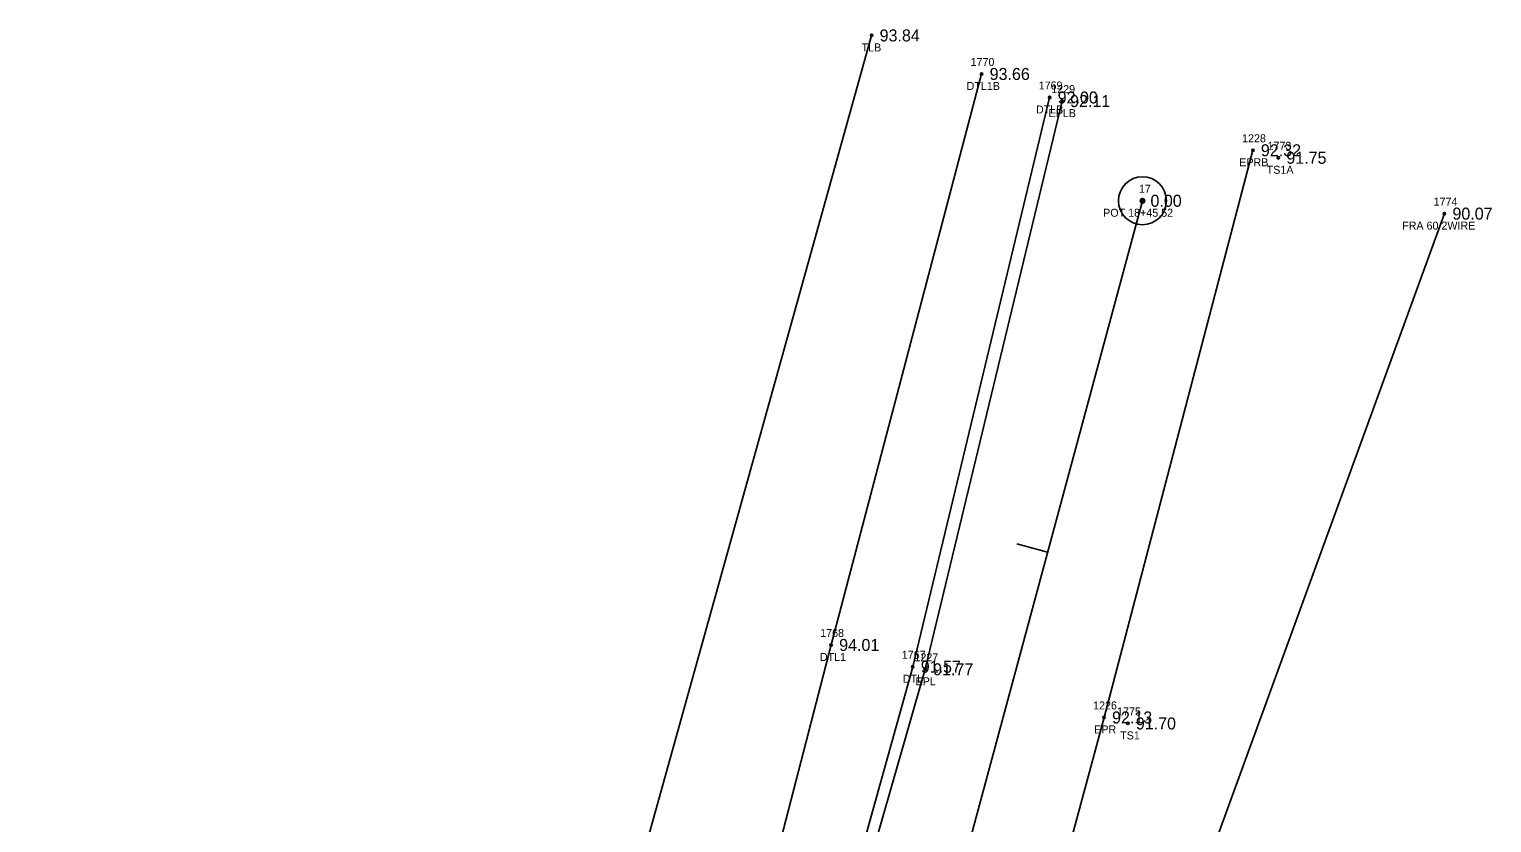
# Model space of a CAD drawing. Extents: x 2529517 to 2532038, y 935000 to 936944.
# Drawn here: x 2531691.2 to 2531874, y 936495.6 to 936594.8 of the extents above; entities that cross this region are included whole.
import ezdxf

# ---------------------------------------------------------------- set-up
doc = ezdxf.new("R2010")
doc.units = 0
for name, color, linetype in [('Default', 7, 'Continuous'), ('RD_DTM_BkLn_txCode', 7, 'Continuous'), ('RD_EX_Fence_Other', 7, 'Continuous'), ('RD_EX_Fence_Other_txCode', 7, 'Continuous'), ('RD_EX_H2O', 7, 'Continuous'), ('RD_EX_H2O_txCode', 7, 'Continuous'), ('RD_EX_Road', 7, 'Continuous'), ('RD_EX_Road_txCode', 7, 'Continuous'), ('RD_EX_TX_Fence_Other_ELEV', 7, 'Continuous'), ('RD_EX_TX_H2O_ELEV', 7, 'Continuous'), ('RD_EX_TX_Misc_ELEV', 7, 'Continuous'), ('RD_EX_TX_Road_ELEV', 7, 'Continuous'), ('RD_EX_TX_VEG_ELEV', 7, 'Continuous'), ('RD_EX_VEG', 7, 'Continuous'), ('RD_EX_VEG_txCode', 7, 'Continuous'), ('RD_HC_Cl', 7, 'Continuous'), ('RD_HC_Data', 7, 'Continuous'), ('RD_HC_Data_Tic', 7, 'Continuous'), ('RD_HC_Survey_ELEV', 7, 'Continuous'), ('RD_HC_txCode', 7, 'Continuous'), ('RD_SMD_Locator', 7, 'Continuous')]:
    doc.layers.add(name, color=color, linetype=linetype)

msp = doc.modelspace()

# ---------------------------------------------------------------- linework, layer by layer
at = {"layer": 'Default'}
msp.add_line((2531768.07, 936342.55), (2531830.33, 936573.34), dxfattribs=at)
at = {"layer": 'RD_EX_Fence_Other'}
msp.add_lwpolyline([(2531868.07, 936571.73), (2531829.55, 936465.97), (2531793.34, 936363.65)], dxfattribs=at)
at = {"layer": 'RD_EX_H2O'}
for points in [[(2531765.74, 936419.97), (2531768.07, 936430.45), (2531772.65, 936445.12), (2531791.42, 936517.8), (2531810.23, 936589.19)], [(2531765.74, 936419.97), (2531771.25, 936418.23), (2531776.62, 936427.07), (2531781.23, 936441.81), (2531801.62, 936515.08), (2531818.73, 936586.25)]]:
    msp.add_lwpolyline(points, dxfattribs=at)
at = {"layer": 'RD_EX_Road'}
for points in [[(2531169.65, 936000.77), (2531208.79, 936024.95), (2531292.04, 936074.02), (2531376.24, 936123.7), (2531460.37, 936174.49), (2531542.92, 936223.44), (2531626.67, 936270.85), (2531672.4, 936298.39), (2531714.28, 936327.21), (2531747.19, 936360.45), (2531761.42, 936377.32), (2531773.11, 936411.11), (2531782.2, 936441.65), (2531803.17, 936514.76), (2531820.28, 936585.8)], [(2531180.82, 935982), (2531220.82, 936004.21), (2531303.54, 936053.39), (2531388.75, 936103.71), (2531472.27, 936152.98), (2531554.79, 936201.9), (2531638.11, 936250.92), (2531683.19, 936278.28), (2531730.37, 936304.55), (2531771.5, 936341.26), (2531788.67, 936375.53), (2531805.57, 936434.84), (2531825.53, 936508.74), (2531844.13, 936579.65)]]:
    msp.add_lwpolyline(points, dxfattribs=at)
at = {"layer": 'RD_EX_VEG'}
msp.add_lwpolyline([(2531707.06, 936475.72), (2531750.92, 936430.42), (2531796.48, 936594.01)], dxfattribs=at)
at = {"layer": 'RD_HC_Cl'}
msp.add_line((2531768.07, 936342.55), (2531830.33, 936573.34), dxfattribs=at)
at = {"layer": 'RD_HC_Data'}
for radius in [3, 0.282]:
    msp.add_circle((2531830.33, 936573.34), radius, dxfattribs=at)
at = {"layer": 'RD_HC_Data_Tic'}
msp.add_line((2531818.47, 936529.39), (2531814.61, 936530.44), dxfattribs=at)
at = {"layer": 'RD_SMD_Locator'}
for centre in [(2531796.48, 936594.01), (2531810.23, 936589.19), (2531818.73, 936586.25), (2531820.28, 936585.8), (2531844.13, 936579.65), (2531847.31, 936578.71), (2531830.33, 936573.34), (2531868.07, 936571.73), (2531791.42, 936517.8), (2531801.62, 936515.08), (2531803.17, 936514.76), (2531825.53, 936508.74), (2531828.5, 936507.99)]:
    msp.add_circle(centre, 0.15, dxfattribs=at)

# ---------------------------------------------------------------- texts
at = {"layer": 'RD_DTM_BkLn_txCode'}
for s, p in [('1773', (2531845.96, 936579.71)), ('TS1A', (2531845.86, 936576.71)), ('1775', (2531827.16, 936508.99)), ('TS1', (2531827.54, 936505.99))]:
    msp.add_text(s, height=1, dxfattribs=at).set_placement(p)
at = {"layer": 'RD_EX_Fence_Other_txCode'}
for s, p in [('1774', (2531866.72, 936572.73)), ('FRA 60 2WIRE', (2531862.79, 936569.73))]:
    msp.add_text(s, height=1, dxfattribs=at).set_placement(p)
at = {"layer": 'RD_EX_H2O_txCode'}
for s, p in [('1770', (2531808.85, 936590.19)), ('DTL1B', (2531808.35, 936587.19)), ('1769', (2531817.36, 936587.25)), ('DTLB', (2531817.02, 936584.25)), ('1768', (2531790.05, 936518.8)), ('DTL1', (2531790.01, 936515.8)), ('1767', (2531800.25, 936516.08)), ('DTL', (2531800.37, 936513.08))]:
    msp.add_text(s, height=1, dxfattribs=at).set_placement(p)
at = {"layer": 'RD_EX_Road_txCode'}
for s, p in [('1229', (2531818.93, 936586.8)), ('EPLB', (2531818.6, 936583.8)), ('1228', (2531842.78, 936580.65)), ('EPRB', (2531842.43, 936577.65)), ('1227', (2531801.83, 936515.76)), ('EPL', (2531801.97, 936512.76)), ('1226', (2531824.16, 936509.74)), ('EPR', (2531824.3, 936506.74))]:
    msp.add_text(s, height=1, dxfattribs=at).set_placement(p)
at = {"layer": 'RD_EX_TX_Fence_Other_ELEV'}
msp.add_text('90.07', height=1.5, dxfattribs=at).set_placement((2531869.07, 936570.98))
at = {"layer": 'RD_EX_TX_H2O_ELEV'}
for s, p in [('93.66', (2531811.23, 936588.44)), ('92.00', (2531819.73, 936585.5)), ('94.01', (2531792.42, 936517.05)), ('91.57', (2531802.62, 936514.33))]:
    msp.add_text(s, height=1.5, dxfattribs=at).set_placement(p)
at = {"layer": 'RD_EX_TX_Misc_ELEV'}
for s, p in [('91.75', (2531848.31, 936577.96)), ('91.70', (2531829.5, 936507.24))]:
    msp.add_text(s, height=1.5, dxfattribs=at).set_placement(p)
at = {"layer": 'RD_EX_TX_Road_ELEV'}
for s, p in [('92.11', (2531821.28, 936585.05)), ('92.32', (2531845.13, 936578.9)), ('91.77', (2531804.17, 936514.01)), ('92.13', (2531826.53, 936507.99))]:
    msp.add_text(s, height=1.5, dxfattribs=at).set_placement(p)
at = {"layer": 'RD_EX_TX_VEG_ELEV'}
msp.add_text('93.84', height=1.5, dxfattribs=at).set_placement((2531797.48, 936593.26))
at = {"layer": 'RD_EX_VEG_txCode'}
msp.add_text('TLB', height=1, dxfattribs=at).set_placement((2531795.23, 936592.01))
at = {"layer": 'RD_HC_Survey_ELEV'}
msp.add_text('0.00', height=1.5, dxfattribs=at).set_placement((2531831.33, 936572.59))
at = {"layer": 'RD_HC_txCode'}
for s, p in [('17', (2531829.88, 936574.34)), ('POT 18+45.52', (2531825.42, 936571.34))]:
    msp.add_text(s, height=1, dxfattribs=at).set_placement(p)

doc.saveas('drawing.dxf')
